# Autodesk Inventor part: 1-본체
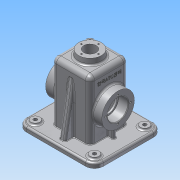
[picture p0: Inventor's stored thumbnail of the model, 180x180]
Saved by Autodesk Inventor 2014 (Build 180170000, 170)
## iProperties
Created: 2015-12
Part Number: 1-본체
Material: 알루미늄 6061
Document SubType Name: Modeling
Designer: Administrator
Density: 2.71 g/cm^3
Appearance: 알루미늄 - 평지
Mass: 802.895 g
Surface Area: 910.456 cm^2
Volume: 296.271 cm^3
Author: Administrator
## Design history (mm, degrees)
sketch "스케치1"
  geometry: L1 (65, -57.5)-(-65, -57.5); L2 (-65, -57.5)-(-65, 57.5); L3 (-65, 57.5)-(65, 57.5); L4 (65, 57.5)-(65, -57.5); L5 (65, -57.5)-(-65, 57.5); L6 (-65, -57.5)-(65, 57.5); 1 further point
  constraints: 12 end point, 2 midpoint, 2 parallel, 1 horizontal, 1 perpendicular
  dimensions: "d0" = 130 distance of L2.end L3.end; "d1" = 115 distance of L3.end L1.start
extrude "돌출1" new body sketch "스케치1" distance "d2" = 8; taper "d3" = 0 deg
node "작업 평면2"
sketch "스케치3"
  geometry: L1 (32.5, -32.5)-(-32.5, -32.5); L2 (-32.5, -32.5)-(-32.5, 32.5); L3 (-32.5, 32.5)-(32.5, 32.5); L4 (32.5, 32.5)-(32.5, -32.5); L5 (32.5, -32.5)-(-32.5, 32.5); L6 (-32.5, -32.5)-(32.5, 32.5); 1 further point
  constraints: 12 end point, 2 midpoint, 2 parallel, 1 horizontal, 1 perpendicular
  dimensions: "d6" = 65 distance of L2.end L3.end; "d7" = 65 distance of L3.end L1.start
extrude "돌출2" join sketch "스케치3" stored distance "d8" = 10; taper "d9" = 0 deg
node "작업 평면5"
sketch "스케치6"
  geometry: L1 (-32.5, 108)-(-32.5, 8) reference; L2 (-57.5, 0)-(-57.5, 8) reference; L3 (57.5, 8)-(-57.5, 8) reference; L4 (-47.5, 8)-(-31.058, 101.247); L5 (-31.058, 101.247)-(-31.058, 8); L6 (-47.5, 8)-(-31.058, 8); 1 further point
  constraints: 6 end point, 2 point on line, 1 collinear, 1 perpendicular
  dimensions: "d21" = 10 distance from line of L4.start L2; "d22" = 10 deg angle of L4 L2; "d23" = 93.24685 distance of L4.end L5.end
extrude "돌출3" join sketch "스케치6" stored distance "d24" = 10; taper "d25" = 0 deg
sketch "스케치7"
  geometry: L1 (60, -52.5)-(-60, -52.5); L2 (-60, -52.5)-(-60, 52.5); L3 (-60, 52.5)-(60, 52.5); L4 (60, 52.5)-(60, -52.5); L5 (60, -52.5)-(-60, 52.5); L6 (-60, -52.5)-(60, 52.5); 1 further point
  constraints: 12 end point, 2 midpoint, 2 parallel, 1 horizontal, 1 perpendicular
  dimensions: "d26" = 120 distance of L2.end L3.end; "d27" = 105 distance of L3.end L1.start
extrude "돌출4" join sketch "스케치7" distance "d28" = 2; taper "d29" = 0 deg
node "작업 평면6"
node "작업 평면7"
sketch "스케치9"
  geometry: L1 (-32.5, 108)-(-32.5, 8) reference; L2 (32.5, 108)-(32.5, 8) reference; L3 (-32.5, 108)-(32.5, 108) reference; L4 (27.5, -2)-(27.5, 103); L5 (27.5, 103)-(-27.5, 103); L6 (-27.5, 103)-(-27.5, -2); L7 (-52.5, -2)-(52.5, -2) reference; 1 further point
  constraints: 6 end point, 2 point on line
  dimensions: "d36" = 5 distance between parallel lines of L6 L1; "d37" = 5 distance between parallel lines of L2 L4; "d38" = 5 distance between parallel lines of L5 L3
extrude "돌출5" cut sketch "스케치9" stored distance "d39" = 55; taper "d40" = 0 deg
node "작업 평면10"
node "작업 평면8"
sketch "스케치22"
  geometry: C1 r 20 at (0, 0); 1 further point
  constraints: 1 centre point, 1 coincident
  dimensions: "d176" = 40 diameter of C1
extrude "돌출12" join sketch "스케치22" distance "d177" = 10; taper "d178" = -5 deg
node "작업 평면9"
fillet "모깎기1" dims "d71" = 15
sketch "스케치15"
  geometry: C1 r 7.5 at (-50, 42.5); C2 r 7.5 at (-50, -42.5); A1 r 15 centre (-50, 42.5) between (-50, 57.5) and (-65, 42.5) reference; A2 r 15 centre (-50, -42.5) between (-65, -42.5) and (-50, -57.5) reference; 1 further point
  constraints: 2 centre point, 2 coincident, 1 equal radius
  dimensions: "d72" = 15 diameter of C1
extrude "돌출9" join sketch "스케치15" distance "d73" = 3; taper "d74" = 0 deg
hole "구멍3" diameter "d77" = 6; stored, may be unused: countersink angle "d81" = 90 deg, drill point angle "d83" = 118 deg; dims "d75" = 10, "d76" = 10, "d78" = 8, "d79" = 35, "d80" = 17, "d82" = 10
hole "구멍4" diameter "d86" = 6; stored, may be unused: countersink angle "d90" = 90 deg, drill point angle "d92" = 118 deg; dims "d84" = 10, "d85" = 10, "d87" = 8, "d88" = 35, "d89" = 17, "d91" = 10
sketch "스케치17"
  geometry: L1 (0, 0)-(100, 0) reference; L2 (-10, 13.375)-(-10, 51.625) reference; 2 further points
  constraints: 1 other
  dimensions: "d103" = 32.5 distance from line of point (16, 32.5) L1; "d196" = 26 distance from line of point (16, 32.5) L2
feature "엠보싱1" sketch "스케치17" dims "d104" = 0.5, "d105" = 0
fillet "모깎기4" dims "d116" = 10
fillet "모깎기8" dims "d125" = 3
fillet "모깎기9" dims "d126" = 1
fillet "모깎기12" dims "d129" = 3
fillet "모깎기13" dims "d130" = 3
fillet "모깎기14" dims "d131" = 3
fillet "모깎기16" dims "d133" = 8
fillet "모깎기17" dims "d134" = 8
sketch "스케치19"
  geometry: L1 (-110, -20)-(-110, 85) reference; L2 (0, 0)-(0, 65) reference; C1 r 27.5 at (-55, 32.5); 2 further points
  constraints: 1 centre point, 1 horizontal alignment, 1 midpoint
  dimensions: "d136" = 55 distance from line of L1 C1.centre; "d137" = 55 diameter of C1
extrude "돌출10" join sketch "스케치19" stored distance "d138" = 3; taper "d139" = 0 deg
hole "구멍7" diameter "d142" = 30; stored, may be unused: countersink angle "d146" = 90 deg, drill point angle "d148" = 0 deg; dims "d143" = 7, "d144" = 35, "d145" = 17, "d147" = 20, "d150" = 10, "d151" = 10
sketch "스케치20"
  geometry: C1 r 17.5 at (0, 0) reference; C2 r 27.5 at (0, 0) reference; A1 r 21 centre (0, 0) between (21, 0) and (0, -21); 3 further points
  constraints: 4 point on circle, 2 horizontal alignment, 2 vertical alignment, 1 centre point, 1 coincident
  dimensions: "d149" = 42 diameter of A1
hole "구멍8" sketch "스케치20" at (21, 0), (0, -21), (-21, 0), (0, 21) diameter "d152" = 3.242; stored, may be unused: countersink angle "d156" = 90 deg, drill point angle "d158" = 118 deg; dims "d153" = 8, "d154" = 42, "d155" = 17, "d157" = 10
fillet "모깎기18" dims "d159" = 3
fillet "모깎기19" dims "d160" = 3
fillet "모깎기20" dims "d161" = 0.3
node "작업 평면11"
sketch "스케치21"
  geometry: L1 (-47.5, 25.5)-(-35.5, 25.5) reference; L2 (-32.5, 9)-(-32.5, 34.834) reference; L3 (-50, 8)-(50, 8) reference; L4 (-42.5, 8)-(-42.5, 26.353); L5 (-42.5, 26.353)-(-28.993, 26.353); L6 (-28.993, 26.353)-(-28.993, 8); L7 (-42.5, 8)-(-28.993, 8); L8 (-27.5, 100)-(-27.5, -2) reference; A1 r 3 centre (-35.5, 22.5) between (-32.5, 22.5) and (-35.5, 25.5) reference; 2 further points
  constraints: 8 end point, 3 perpendicular, 2 point on line, 1 collinear
  dimensions: "d163" = 15 distance between parallel lines of L4 L8; "d164" = 18.35318 distance of L4.start L4.end; "d171" = 13.50681 distance of L4.end L5.end
extrude "돌출11" join sketch "스케치21" stored distance "d166" = 6; taper "d167" = 0 deg
fillet "모깎기21" dims "d168" = 3
fillet "모깎기22" dims "d169" = 1
fillet "모깎기24" dims "d172" = 1
chamfer "모따기2" distance "d173" = 1; stored, may be unused: second distance "d174" = 2, angle "d175" = 45 deg
sketch "스케치23"
  geometry: C1 r 19.125 at (0, 0) reference; A1 r 14.5 centre (0, 0) between (0, 14.5) and (14.5, 0); 2 further points
  constraints: 4 point on circle, 2 horizontal alignment, 2 vertical alignment, 1 centre point, 1 coincident
  dimensions: "d179" = 29 diameter of A1
hole "구멍9" sketch "스케치23" at (0, 14.5), (14.5, 0), (-14.5, 0), (0, -14.5) diameter "d180" = 2.459; stored, may be unused: countersink angle "d184" = 90 deg, drill point angle "d186" = 118 deg; dims "d181" = 7, "d182" = 42, "d183" = 17, "d185" = 9
hole "구멍10" diameter "d189" = 21; stored, may be unused: countersink angle "d193" = 90 deg, drill point angle "d195" = 118 deg; dims "d187" = 10, "d188" = 10, "d190" = 7, "d191" = 42, "d192" = 17, "d194" = 9
fillet "모깎기25" dims "d197" = 3
node "솔리드1"
mirror "대칭1"
mirror "대칭4"
mirror "대칭5"
mirror "대칭6"
other parameters: "d5" = 108, "d17" = 0, "d30" = 0, "d35" = 0, "d66" = 0, "d135" = 15, "d162" = 0
